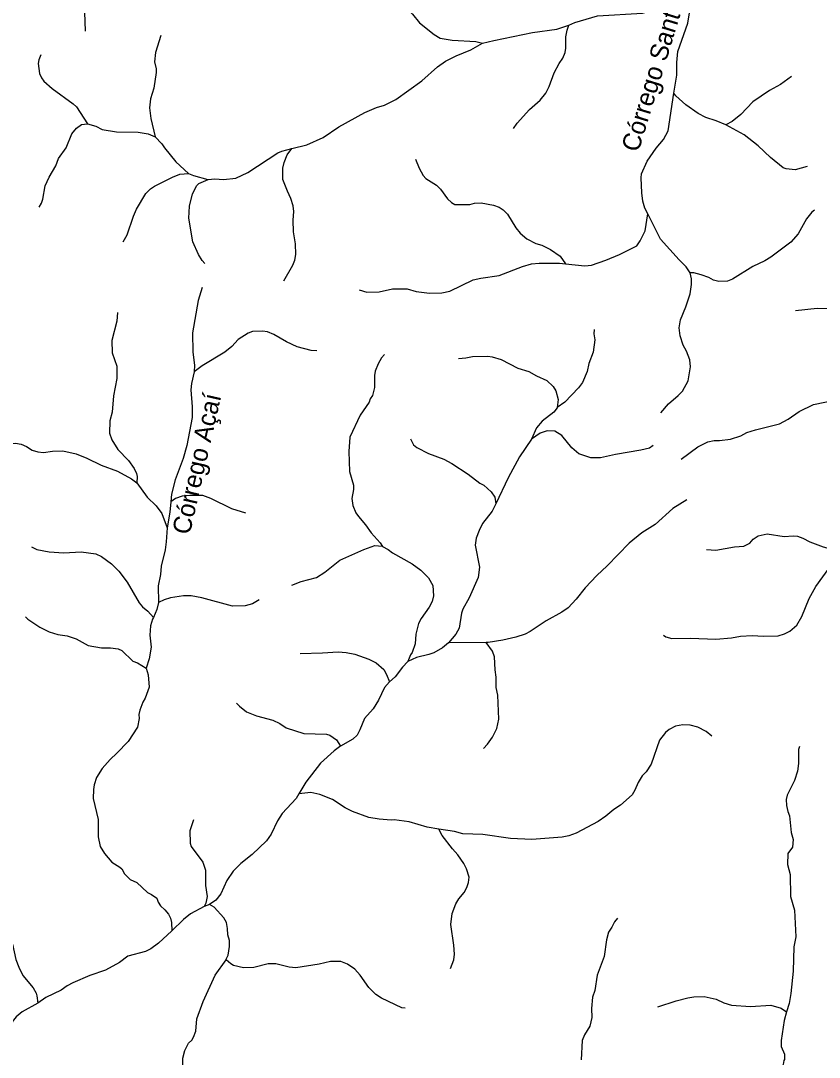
# Model space of a CAD drawing. Extents: x 500 to 555.2, y 9115.7 to 9171.
# Drawn here: x 513.43 to 520.45, y 9152.3 to 9161.41 of the extents above; entities that cross this region are included whole.
import ezdxf
from ezdxf.enums import TextEntityAlignment as Align

# ---------------------------------------------------------------- set-up
doc = ezdxf.new("R2010")
doc.units = 0
doc.header["$LTSCALE"] = 0.064
doc.layers.add('61', color=7, linetype='Continuous')
doc.layers.add('7', color=7, linetype='Continuous', lineweight=25)

msp = doc.modelspace()

# ---------------------------------------------------------------- linework, layer by layer
at = {"layer": '7'}
msp.add_line((515.0903, 9153.6439), (515.0415, 9153.626), dxfattribs=at)
for points in [[(513.9998, 9161.3235), (513.9898, 9161.5709), (514.0026, 9161.6679), (514.034, 9161.8262), (514.0339, 9161.9219), (514.0242, 9161.9895), (514.0274, 9162.1082), (514.0376, 9162.1455), (514.1244, 9162.3341), (514.1357, 9162.3844), (514.141, 9162.467), (514.1863, 9162.5385)], [(518.2508, 9161.3742), (518.3017, 9161.3993), (518.5027, 9161.4571), (518.8985, 9161.4806), (518.9648, 9161.5002), (519.1347, 9161.5247), (519.2069, 9161.5492), (519.3168, 9161.6127)], [(519.1741, 9160.7762), (519.1982, 9160.935), (519.1994, 9161.0459), (519.2074, 9161.1437), (519.296, 9161.3937), (519.314, 9161.5013), (519.3168, 9161.6127)], [(516.841, 9161.5015), (516.8746, 9161.4711), (516.9369, 9161.3974), (517.064, 9161.2928), (517.1179, 9161.2626), (517.2221, 9161.2428), (517.4321, 9161.2312), (517.4888, 9161.2162)], [(517.4888, 9161.2162), (517.5885, 9161.2414), (517.9307, 9161.3115), (518.1431, 9161.34), (518.2508, 9161.3742)], [(517.7635, 9160.4664), (517.7956, 9160.5148), (517.9028, 9160.6335), (517.9974, 9160.7167), (518.0461, 9160.7769), (518.076, 9160.8365), (518.1214, 9160.9569), (518.1653, 9161.0395), (518.197, 9161.0853), (518.2163, 9161.1365), (518.2232, 9161.1732), (518.2218, 9161.2722), (518.234, 9161.3313), (518.2508, 9161.3742)], [(514.6595, 9161.2852), (514.6131, 9161.1339), (514.6066, 9161.0524), (514.6196, 9160.9928), (514.6196, 9160.9602), (514.5982, 9160.8228), (514.5702, 9160.7264), (514.5623, 9160.6495), (514.5718, 9160.5552), (514.6102, 9160.3949)], [(515.8132, 9160.2899), (515.9451, 9160.3221), (516.0877, 9160.3866), (516.2274, 9160.4808), (516.4558, 9160.6082), (516.5569, 9160.6506), (516.629, 9160.672), (516.7268, 9160.7224), (516.9565, 9160.8847), (517.0933, 9161.0081), (517.1659, 9161.0578), (517.2594, 9161.1069), (517.3862, 9161.1588), (517.4888, 9161.2162)], [(513.6066, 9161.1138), (513.5881, 9161.0703), (513.5814, 9161.0387), (513.593, 9160.9508), (513.6104, 9160.9129), (513.6332, 9160.8825), (513.7039, 9160.82), (513.8913, 9160.6834), (513.9192, 9160.6571), (514.0165, 9160.5083)], [(520.2085, 9160.9236), (520.1096, 9160.8524), (520.014, 9160.8012), (519.8686, 9160.7014), (519.7635, 9160.5899), (519.6865, 9160.5277), (519.6313, 9160.5001)], [(518.9434, 9159.717), (518.919, 9159.765), (518.9008, 9159.8289), (518.8909, 9159.9017), (518.8844, 9160.034), (518.8876, 9160.0677), (518.9385, 9160.1792), (519.0183, 9160.2927), (519.0828, 9160.3701), (519.1242, 9160.447), (519.1741, 9160.7762)], [(519.6313, 9160.5001), (519.546, 9160.5329), (519.4554, 9160.5639), (519.3862, 9160.5978), (519.2775, 9160.6757), (519.1893, 9160.7555), (519.1741, 9160.7762)], [(513.5903, 9159.7744), (513.6116, 9159.8112), (513.6223, 9159.8453), (513.643, 9159.9621), (513.6782, 9160.0387), (513.7385, 9160.1374), (513.7611, 9160.2017), (513.8283, 9160.2981), (513.8775, 9160.4194), (513.92, 9160.4709), (513.9622, 9160.5014), (514.0155, 9160.5086), (514.0165, 9160.5083)], [(514.0165, 9160.5083), (514.0899, 9160.4869), (514.1463, 9160.4585), (514.2696, 9160.4374), (514.4605, 9160.4357), (514.5485, 9160.421), (514.6102, 9160.3949)], [(520.3441, 9160.132), (520.2403, 9160.1044), (520.1595, 9160.1111), (520.1331, 9160.1213), (520.0223, 9160.2115), (519.9149, 9160.3155), (519.7921, 9160.4101), (519.6313, 9160.5001)], [(514.6102, 9160.3949), (514.67, 9160.3328), (514.6928, 9160.2968), (514.7917, 9160.1733), (514.9043, 9160.0711)], [(515.0767, 9160.0191), (515.137, 9160.0232), (515.2117, 9160.0191), (515.32, 9160.0307), (515.4256, 9160.0801), (515.6914, 9160.2539), (515.7259, 9160.2686), (515.8132, 9160.2899)], [(515.7429, 9159.1264), (515.8208, 9159.2641), (515.8403, 9159.3083), (515.8482, 9159.3597), (515.8465, 9159.4515), (515.8269, 9159.5571), (515.8237, 9159.6615), (515.8317, 9159.7369), (515.825, 9159.7867), (515.8052, 9159.8524), (515.7747, 9159.9152), (515.7353, 9160.0186), (515.7348, 9160.1188), (515.7458, 9160.1681), (515.7723, 9160.2362), (515.8132, 9160.2899)], [(516.9007, 9160.198), (516.9325, 9160.1176), (516.9677, 9160.0545), (516.9925, 9160.027), (517.086, 9159.9689), (517.1203, 9159.9327), (517.1822, 9159.8497), (517.2168, 9159.817), (517.2469, 9159.7995), (517.3781, 9159.799), (517.4202, 9159.8107), (517.478, 9159.8141), (517.5857, 9159.7915), (517.6366, 9159.7744), (517.6728, 9159.7528), (517.7099, 9159.714), (517.7838, 9159.5926), (517.8215, 9159.5466), (517.8793, 9159.4964), (517.9587, 9159.4544), (518.0132, 9159.4398), (518.087, 9159.4039), (518.1721, 9159.3453), (518.2187, 9159.2774)], [(514.3291, 9159.47), (514.3658, 9159.5315), (514.4206, 9159.6972), (514.4468, 9159.7582), (514.5281, 9159.8948), (514.5709, 9159.9358), (514.6044, 9159.9596), (514.7626, 9160.0398), (514.8293, 9160.0649), (514.9043, 9160.0711)], [(514.9043, 9160.0711), (514.9046, 9160.0709), (514.948, 9160.0524), (515.0746, 9160.019), (515.0767, 9160.0191)], [(515.0487, 9159.2789), (515.0245, 9159.3062), (514.991, 9159.3587), (514.9427, 9159.4701), (514.9085, 9159.6774), (514.9117, 9159.7835), (514.9401, 9159.8932), (514.9769, 9159.9661), (514.9953, 9159.9838), (515.0767, 9160.0191)], [(520.4099, 9159.7491), (520.3853, 9159.7302), (520.3406, 9159.6741), (520.2678, 9159.5395), (520.201, 9159.4674), (520.0271, 9159.3348), (519.973, 9159.3021), (519.8675, 9159.2549), (519.6902, 9159.1435), (519.6458, 9159.1249), (519.569, 9159.1218), (519.5215, 9159.1337), (519.4814, 9159.1562), (519.4136, 9159.1811), (519.3482, 9159.1969), (519.3175, 9159.1977)], [(518.2187, 9159.2774), (518.39, 9159.2597), (518.4497, 9159.2663), (518.5737, 9159.3086), (518.6963, 9159.3583), (518.8464, 9159.434), (518.8778, 9159.4778), (518.9199, 9159.5682), (518.9434, 9159.717)], [(519.3175, 9159.1977), (519.2812, 9159.25), (519.2186, 9159.3109), (519.0563, 9159.4949), (518.9434, 9159.717)], [(516.4039, 9159.0481), (516.4737, 9159.027), (516.5809, 9159.0303), (516.6984, 9159.0562), (516.8286, 9159.0562), (516.9067, 9159.0352), (517.0233, 9159.0204), (517.1329, 9159.0233), (517.2019, 9159.0359), (517.4071, 9159.135), (517.4744, 9159.1517), (517.6364, 9159.1736), (517.841, 9159.2541), (517.921, 9159.2759), (517.9898, 9159.2842), (518.1683, 9159.2826), (518.2187, 9159.2774)], [(519.0574, 9157.9676), (519.1271, 9158.0458), (519.2124, 9158.1181), (519.2487, 9158.1574), (519.2993, 9158.2477), (519.3189, 9158.371), (519.3122, 9158.4319), (519.2855, 9158.508), (519.2561, 9158.5608), (519.2288, 9158.6451), (519.2207, 9158.714), (519.2315, 9158.7837), (519.2793, 9158.8999), (519.3169, 9159.0131), (519.3288, 9159.0939), (519.3288, 9159.1464), (519.3175, 9159.1977)], [(515.0232, 9159.07), (514.9905, 9158.9533), (514.9395, 9158.6702), (514.9428, 9158.4997), (514.9558, 9158.3846), (514.9535, 9158.3266)], [(514.2792, 9158.8482), (514.2749, 9158.7719), (514.2292, 9158.6043), (514.2342, 9158.4936), (514.2735, 9158.3782), (514.2751, 9158.2678), (514.2439, 9158.1158), (514.232, 9157.972), (514.2129, 9157.8959), (514.2093, 9157.7872), (514.2293, 9157.7295), (514.2837, 9157.6453), (514.3768, 9157.5471), (514.4277, 9157.4765), (514.4471, 9157.4336), (514.452, 9157.4067), (514.4503, 9157.3506)], [(520.2434, 9158.8662), (520.4344, 9158.8872), (520.6483, 9158.8809), (520.716, 9158.8889), (520.9183, 9158.8906), (520.9608, 9158.8799), (521.0426, 9158.8278)], [(516.0333, 9158.5116), (515.984, 9158.5151), (515.8589, 9158.5471), (515.7668, 9158.5918), (515.6557, 9158.6554), (515.5995, 9158.6787), (515.556, 9158.6856), (515.4682, 9158.6806), (515.4296, 9158.6663), (515.34, 9158.612), (515.286, 9158.5499), (515.2245, 9158.4995), (515.0254, 9158.3792), (514.9535, 9158.3266)], [(518.471, 9158.6993), (518.4704, 9158.661), (518.4792, 9158.6084), (518.4648, 9158.4991), (518.4257, 9158.4006), (518.4112, 9158.331), (518.3694, 9158.2346), (518.3347, 9158.1853), (518.2147, 9158.0617), (518.1481, 9158.0131)], [(516.6282, 9158.4787), (516.6029, 9158.4491), (516.5713, 9158.398), (516.5455, 9158.3335), (516.5388, 9158.2941), (516.5403, 9158.1891), (516.5238, 9158.1185), (516.5028, 9158.0901), (516.4921, 9158.0602), (516.4142, 9157.9464), (516.3229, 9157.7539), (516.3141, 9157.6282), (516.3206, 9157.4511), (516.3566, 9157.3317), (516.3566, 9157.2919), (516.3403, 9157.2136), (516.3487, 9157.1512), (516.3773, 9157.0876), (516.3982, 9157.0545), (516.4612, 9156.9819), (516.5121, 9156.9122), (516.5896, 9156.8247), (516.6099, 9156.7928)], [(517.2802, 9158.4444), (517.3435, 9158.4493), (517.4032, 9158.4624), (517.5363, 9158.4658), (517.5749, 9158.4595), (517.6538, 9158.4354), (517.7996, 9158.361), (517.898, 9158.3297), (517.9646, 9158.2909), (518.0548, 9158.2499), (518.1114, 9158.1987), (518.1363, 9158.1618), (518.1543, 9158.0856), (518.1481, 9158.0131)], [(514.9535, 9158.3266), (514.9299, 9158.2261), (514.9249, 9158.1698), (514.9378, 9158.0186), (514.9361, 9157.9268), (514.8891, 9157.6791), (514.8574, 9157.5653), (514.7883, 9157.3776), (514.756, 9157.2518), (514.7496, 9157.1851)], [(519.2365, 9157.5609), (519.3842, 9157.6682), (519.4722, 9157.7107), (519.5263, 9157.7243), (519.5745, 9157.7228), (519.672, 9157.7362), (519.7627, 9157.7647), (519.8145, 9157.7932), (519.8907, 9157.8187), (520.1031, 9157.8704), (520.178, 9157.911), (520.2748, 9157.9799), (520.4011, 9158.0389), (520.5845, 9158.0775), (520.6568, 9158.1021), (520.7001, 9158.1263), (520.7571, 9158.1711), (520.8714, 9158.2346), (520.9757, 9158.2574), (521.097, 9158.2483)], [(518.1481, 9158.0131), (518.1471, 9158.0123), (518.1167, 9157.9738), (518.0162, 9157.893), (517.9642, 9157.8356), (517.9223, 9157.7368)], [(516.8558, 9157.7377), (516.8835, 9157.6854), (516.9115, 9157.6619), (517.0156, 9157.6098), (517.1512, 9157.56), (517.219, 9157.5228), (517.3647, 9157.4267), (517.4664, 9157.3498), (517.502, 9157.3302), (517.5672, 9157.2715), (517.598, 9157.2253), (517.6059, 9157.1669)], [(517.9223, 9157.7368), (517.8162, 9157.581), (517.7156, 9157.3961), (517.6059, 9157.1669)], [(518.9916, 9157.6793), (518.9586, 9157.6558), (518.8833, 9157.6375), (518.6584, 9157.601), (518.5279, 9157.5717), (518.4437, 9157.5702), (518.3366, 9157.6063), (518.2769, 9157.6595), (518.1889, 9157.7685), (518.125, 9157.8062), (518.0599, 9157.8079), (517.9971, 9157.7882), (517.9223, 9157.7368)], [(513.2219, 9157.6625), (513.3005, 9157.6901), (513.3818, 9157.6997), (513.4324, 9157.6908), (513.4791, 9157.6704), (513.5297, 9157.639), (513.5786, 9157.6226), (513.6278, 9157.6178), (513.7087, 9157.6308), (513.799, 9157.632), (513.9171, 9157.6058), (514.01, 9157.5689), (514.1363, 9157.5076), (514.279, 9157.4541), (514.4025, 9157.3858), (514.4503, 9157.3506)], [(514.4503, 9157.3506), (514.5399, 9157.2254), (514.6196, 9157.1502), (514.6711, 9157.0812), (514.7169, 9156.956)], [(514.7496, 9157.1851), (514.7408, 9157.0944), (514.7169, 9156.956)], [(515.4095, 9157.084), (515.2867, 9157.1242), (515.1002, 9157.2141), (515.0307, 9157.2388), (514.9159, 9157.2404), (514.8483, 9157.2339), (514.7914, 9157.213), (514.7496, 9157.1851)], [(519.2876, 9157.2021), (519.1649, 9157.1256), (519.0097, 9156.9838), (518.89, 9156.9116), (518.7794, 9156.8205), (518.5858, 9156.6205), (518.4956, 9156.5367), (518.3942, 9156.4285), (518.3139, 9156.3273), (518.2435, 9156.2534), (518.1883, 9156.2134), (518.0489, 9156.1395), (517.9098, 9156.0456), (517.8647, 9156.022), (517.7818, 9155.9958), (517.6676, 9155.969), (517.5401, 9155.9475), (517.5229, 9155.9473), (517.1912, 9155.944)], [(517.6059, 9157.1669), (517.5755, 9157.1033), (517.4911, 9156.9925), (517.4613, 9156.9334), (517.4358, 9156.8658), (517.4262, 9156.8023), (517.4622, 9156.6105), (517.4507, 9156.5188), (517.3727, 9156.3398), (517.3163, 9156.2398), (517.3062, 9156.2055), (517.2849, 9156.075), (517.2548, 9156.0213), (517.1912, 9155.944)], [(514.7169, 9156.956), (514.7082, 9156.8336), (514.6983, 9156.7615), (514.6641, 9156.6178), (514.6588, 9156.5443), (514.6378, 9156.4472), (514.641, 9156.3003), (514.6405, 9156.2983)], [(519.4614, 9156.7664), (519.5427, 9156.7584), (519.7073, 9156.7874), (519.7887, 9156.7944), (519.8409, 9156.8215), (519.8695, 9156.8576), (519.915, 9156.8855), (519.9925, 9156.9026), (520.1444, 9156.8797), (520.2222, 9156.8846), (520.2606, 9156.8812), (520.3071, 9156.8662), (520.3701, 9156.8331), (520.4863, 9156.7895), (520.5709, 9156.7667), (520.6903, 9156.7539)], [(513.5236, 9156.7876), (513.5716, 9156.7666), (513.6798, 9156.7435), (513.8071, 9156.7353), (513.9592, 9156.745), (514.0898, 9156.727), (514.139, 9156.7024), (514.2274, 9156.6405), (514.2902, 9156.5757), (514.3649, 9156.4767), (514.4708, 9156.2951), (514.4988, 9156.2624), (514.5473, 9156.2234), (514.5954, 9156.1661)], [(515.8122, 9156.4511), (515.8962, 9156.4838), (516.0286, 9156.5188), (516.1031, 9156.5672), (516.2364, 9156.6707), (516.4453, 9156.7664), (516.5443, 9156.7992), (516.6074, 9156.7942), (516.6099, 9156.7928)], [(516.6099, 9156.7928), (516.6597, 9156.7648), (516.6978, 9156.7353), (516.87, 9156.6384), (516.9488, 9156.5843), (517.0157, 9156.5159), (517.0521, 9156.4492), (517.0587, 9156.3579), (517.0472, 9156.3088), (517.0223, 9156.2586), (516.9493, 9156.1583), (516.9275, 9156.1152), (516.9048, 9156.0214), (516.8975, 9155.936), (516.87, 9155.8594), (516.8562, 9155.8379), (516.8334, 9155.7802)], [(519.0812, 9156.0109), (519.1028, 9155.9979), (519.1556, 9155.9824), (519.3202, 9155.9871), (519.5427, 9155.9775), (519.6811, 9155.989), (519.7587, 9156.0038), (519.8629, 9156.0087), (519.9606, 9156.0037), (520.0918, 9156.0053), (520.145, 9156.0231), (520.1927, 9156.0483), (520.2543, 9156.0993), (520.2999, 9156.1776), (520.362, 9156.3344), (520.4216, 9156.4409), (520.5669, 9156.6428), (520.64, 9156.7177), (520.6903, 9156.7539)], [(514.6405, 9156.2983), (514.6267, 9156.2386), (514.5954, 9156.1661)], [(515.5271, 9156.3219), (515.4672, 9156.289), (515.4037, 9156.269), (515.29, 9156.2661), (515.0221, 9156.3397), (514.929, 9156.3579), (514.8607, 9156.3579), (514.7466, 9156.3416), (514.6913, 9156.324), (514.6405, 9156.2983)], [(513.4718, 9156.1724), (513.4922, 9156.1535), (513.5979, 9156.0827), (513.6785, 9156.0419), (513.7553, 9156.0192), (513.8372, 9156.0053), (513.9165, 9155.9804), (514.0215, 9155.92), (514.1377, 9155.9005), (514.2178, 9155.9003), (514.2859, 9155.8905), (514.3188, 9155.8776), (514.415, 9155.7849), (514.4572, 9155.7691), (514.5329, 9155.7232)], [(514.5954, 9156.1661), (514.589, 9156.1514), (514.5707, 9156.0931), (514.5655, 9156.0129), (514.5752, 9155.9079), (514.5589, 9155.8035), (514.5329, 9155.7232)], [(517.1912, 9155.944), (517.1391, 9155.8994), (517.0629, 9155.8581), (517.0178, 9155.8408), (516.9104, 9155.8147), (516.8334, 9155.7802)], [(517.4983, 9155.0158), (517.5338, 9155.0533), (517.5785, 9155.1146), (517.6175, 9155.1921), (517.6344, 9155.2721), (517.6246, 9155.4853), (517.6107, 9155.5531), (517.6114, 9155.6428), (517.6013, 9155.7084), (517.5952, 9155.822), (517.577, 9155.8707), (517.5229, 9155.9473)], [(515.8856, 9155.851), (516.0817, 9155.8561), (516.2219, 9155.8659), (516.2906, 9155.8609), (516.3683, 9155.8455), (516.4894, 9155.8013), (516.5547, 9155.7697), (516.621, 9155.7095), (516.647, 9155.6656), (516.6709, 9155.6004)], [(516.8334, 9155.7802), (516.7876, 9155.7308), (516.7224, 9155.6461), (516.6709, 9155.6004)], [(514.5329, 9155.7232), (514.5493, 9155.6633), (514.5571, 9155.5558), (514.5225, 9155.4585), (514.5025, 9155.4216), (514.4756, 9155.3515), (514.4688, 9155.3141), (514.4702, 9155.278), (514.4552, 9155.2027), (514.3725, 9155.0781), (514.2748, 9154.9748), (514.2141, 9154.9189), (514.1444, 9154.8396), (514.0965, 9154.7594), (514.0752, 9154.6954), (514.0685, 9154.6546), (514.0672, 9154.5751), (514.1097, 9154.3899), (514.1112, 9154.2381), (514.1264, 9154.1545), (514.1657, 9154.0938), (514.2297, 9154.0154), (514.3015, 9153.9717), (514.3188, 9153.9569), (514.3413, 9153.9134), (514.3913, 9153.8625), (514.4485, 9153.8372), (514.5427, 9153.7495), (514.5792, 9153.733), (514.6257, 9153.6992), (514.6385, 9153.6632), (514.6589, 9153.6312), (514.6975, 9153.5972), (514.7281, 9153.559), (514.7452, 9153.525), (514.7557, 9153.4866), (514.7566, 9153.4119)], [(516.6709, 9155.6004), (516.628, 9155.5524), (516.5756, 9155.4406), (516.5276, 9155.3651), (516.4517, 9155.2781), (516.4121, 9155.1796), (516.3872, 9155.1323), (516.35, 9155.0983), (516.2414, 9155.0349)], [(515.3259, 9155.4154), (515.3528, 9155.3871), (515.4152, 9155.3386), (515.5018, 9155.3022), (515.6466, 9155.2635), (515.7083, 9155.2342), (515.7641, 9155.197), (515.9192, 9155.1462), (516.119, 9155.1426), (516.1486, 9155.1316), (516.2056, 9155.0915), (516.2414, 9155.0349)], [(519.5076, 9155.1244), (519.4568, 9155.1638), (519.3851, 9155.2045), (519.3178, 9155.2197), (519.2529, 9155.2228), (519.1878, 9155.2114), (519.1305, 9155.182), (519.1001, 9155.1548), (519.0457, 9155.0889), (518.9746, 9154.8791), (518.9302, 9154.811), (518.894, 9154.7746), (518.8597, 9154.7174), (518.8308, 9154.6487), (518.8059, 9154.6083), (518.7032, 9154.5166), (518.646, 9154.4799), (518.5752, 9154.4198), (518.5073, 9154.3724), (518.3125, 9154.2718), (518.2482, 9154.2481), (518.1899, 9154.2354), (517.9242, 9154.2142), (517.7357, 9154.225), (517.4932, 9154.2582), (517.3166, 9154.265), (517.2439, 9154.2868), (517.1073, 9154.3071)], [(516.2414, 9155.0349), (516.2316, 9155.0292), (516.184, 9154.995), (516.0655, 9154.8872), (515.9355, 9154.7199), (515.8737, 9154.6162)], [(520.277, 9155.0338), (520.2691, 9155.0075), (520.2704, 9154.885), (520.2605, 9154.8162), (520.233, 9154.7354), (520.1691, 9154.6067), (520.1622, 9154.5667), (520.1638, 9154.515), (520.1751, 9154.4624), (520.1915, 9154.4224), (520.205, 9154.2775), (520.2228, 9154.2151), (520.2154, 9154.149), (520.1769, 9154.0936), (520.1721, 9153.9954), (520.1949, 9153.9074), (520.1985, 9153.7156), (520.2343, 9153.5951), (520.2457, 9153.3589), (520.2294, 9153.2703), (520.2211, 9153.0577), (520.2012, 9152.8626), (520.1863, 9152.7725), (520.1652, 9152.7014)], [(515.8737, 9154.6162), (515.8498, 9154.5762), (515.7269, 9154.4453), (515.6862, 9154.3804), (515.6303, 9154.2623), (515.591, 9154.2032), (515.4655, 9154.0841), (515.366, 9154.0057), (515.2983, 9153.938), (515.24, 9153.8555), (515.1896, 9153.7382), (515.1433, 9153.6831), (515.0903, 9153.6439)], [(517.1073, 9154.3071), (517.0048, 9154.3235), (516.8455, 9154.3716), (516.7143, 9154.3879), (516.6866, 9154.3848), (516.5824, 9154.3929), (516.4896, 9154.4096), (516.347, 9154.4624), (516.2823, 9154.4949), (516.1703, 9154.568), (516.0587, 9154.6124), (515.9808, 9154.6274), (515.8737, 9154.6162)], [(514.9476, 9154.3888), (514.9168, 9154.2926), (514.918, 9154.1843), (514.9274, 9154.1532), (515.03, 9154.0151), (515.0542, 9153.9467), (515.0543, 9153.8116), (515.069, 9153.7144), (515.0573, 9153.6547), (515.0415, 9153.626)], [(517.2084, 9153.0808), (517.2376, 9153.1568), (517.244, 9153.2086), (517.2392, 9153.2867), (517.2113, 9153.4678), (517.2245, 9153.5662), (517.2546, 9153.6493), (517.281, 9153.6942), (517.3294, 9153.75), (517.3517, 9153.7929), (517.367, 9153.8385), (517.372, 9153.8856), (517.3506, 9153.9566), (517.3263, 9154.0054), (517.2734, 9154.08), (517.2248, 9154.1326), (517.1366, 9154.2504), (517.1073, 9154.3071)], [(513.0649, 9154.0301), (513.1078, 9153.9285), (513.15, 9153.8051), (513.2194, 9153.6862), (513.2397, 9153.602), (513.2582, 9153.5432), (513.2763, 9153.4497), (513.3572, 9153.2966), (513.3869, 9153.16), (513.411, 9153.0932), (513.4473, 9153.0211), (513.5382, 9152.9123), (513.5654, 9152.8629), (513.5715, 9152.8415), (513.5793, 9152.7762)], [(515.2342, 9153.1587), (515.2368, 9153.1625), (515.2542, 9153.1974), (515.2642, 9153.2742), (515.2642, 9153.3261), (515.2497, 9153.3786), (515.2477, 9153.4331), (515.2373, 9153.4855), (515.2165, 9153.5267), (515.1296, 9153.6203), (515.0903, 9153.6439)], [(515.0415, 9153.626), (514.9226, 9153.5625), (514.8617, 9153.5118), (514.7566, 9153.4119)], [(518.6765, 9153.5241), (518.6514, 9153.4917), (518.628, 9153.4435), (518.5974, 9153.3998), (518.581, 9153.3344), (518.5611, 9153.1857), (518.4989, 9153.0216), (518.4774, 9152.8866), (518.4582, 9152.8286), (518.4481, 9152.7283), (518.4529, 9152.6509), (518.4346, 9152.575), (518.3874, 9152.4968), (518.3677, 9152.4475), (518.3575, 9152.2781)], [(514.7566, 9153.4119), (514.6414, 9153.3025), (514.5732, 9153.2552), (514.5265, 9153.2312), (514.372, 9153.1904), (514.2981, 9153.1344), (514.1755, 9153.0669), (514.0379, 9153.0201), (513.8859, 9152.9565), (513.8362, 9152.929), (513.7842, 9152.8901), (513.6483, 9152.8252), (513.5793, 9152.7762)], [(514.914, 9151.8978), (514.9068, 9151.9238), (514.8968, 9152.0566), (514.8544, 9152.2382), (514.8542, 9152.2928), (514.8725, 9152.3594), (514.905, 9152.4258), (514.9322, 9152.4517), (514.9486, 9152.4765), (514.9674, 9152.5301), (514.9772, 9152.6372), (515.0347, 9152.792), (515.1402, 9153.0228), (515.2342, 9153.1587)], [(516.8101, 9152.7333), (516.7806, 9152.7359), (516.6005, 9152.8193), (516.5531, 9152.853), (516.4908, 9152.9154), (516.4141, 9153.0232), (516.3661, 9153.0744), (516.3019, 9153.1194), (516.2443, 9153.1413), (516.154, 9153.1429), (516.0535, 9153.1198), (515.8489, 9153.0873), (515.7891, 9153.0922), (515.6717, 9153.1216), (515.6061, 9153.1233), (515.479, 9153.0907), (515.3883, 9153.0875), (515.3004, 9153.1086), (515.2752, 9153.1222), (515.2342, 9153.1587)], [(519.032, 9152.7452), (519.1922, 9152.7972), (519.2956, 9152.8246), (519.3486, 9152.8329), (519.4399, 9152.836), (519.5454, 9152.8116), (519.6138, 9152.7792), (519.6788, 9152.7578), (519.8457, 9152.7478), (520.027, 9152.7575), (520.1156, 9152.7314), (520.1652, 9152.7014)], [(513.5793, 9152.7762), (513.4408, 9152.7005), (513.3889, 9152.6569), (513.3655, 9152.6281), (513.2618, 9152.4415), (513.198, 9152.3568), (513.0717, 9152.2871), (513.027, 9152.2506), (512.9891, 9152.2068), (512.9701, 9152.1727), (512.9417, 9152.0866), (512.9372, 9151.9834), (512.9364, 9151.9792)], [(520.1652, 9152.7014), (520.1442, 9152.6231), (520.1164, 9152.4482), (520.1181, 9152.3967), (520.1456, 9152.3294), (520.1458, 9152.2824), (520.1394, 9152.2718), (520.1358, 9152.2367), (520.1161, 9152.2025), (520.1098, 9152.1752), (520.1189, 9152.073), (520.1508, 9152.004), (520.1605, 9151.9679), (520.1603, 9151.9318), (520.1392, 9151.8603), (520.1262, 9151.7888), (520.1359, 9151.4076), (520.1575, 9151.2532), (520.16, 9151.1965)]]:
    msp.add_lwpolyline(points, dxfattribs=at)

# ---------------------------------------------------------------- texts
at = {"layer": '61'}
for s, rotation, p in [('Córrego Santa Fé', 73.072, (519.1084, 9161.0645)), ('Córrego Açaí', 77.196, (515.0541, 9157.502))]:
    msp.add_text(s, height=0.16, rotation=rotation, dxfattribs=at).set_placement(p, align=Align.CENTER)

doc.saveas('drawing.dxf')
